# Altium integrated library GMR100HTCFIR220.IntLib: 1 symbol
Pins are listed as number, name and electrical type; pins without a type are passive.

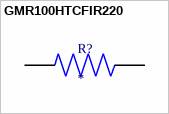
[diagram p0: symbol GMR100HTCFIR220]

## GMR100HTCFIR220
designator R?
Current Sense Res, Aec-Q200, 0R22, 2512; MP: GMR100HTCFIR220
footprint RESC6432X55N
pins: 1, 2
